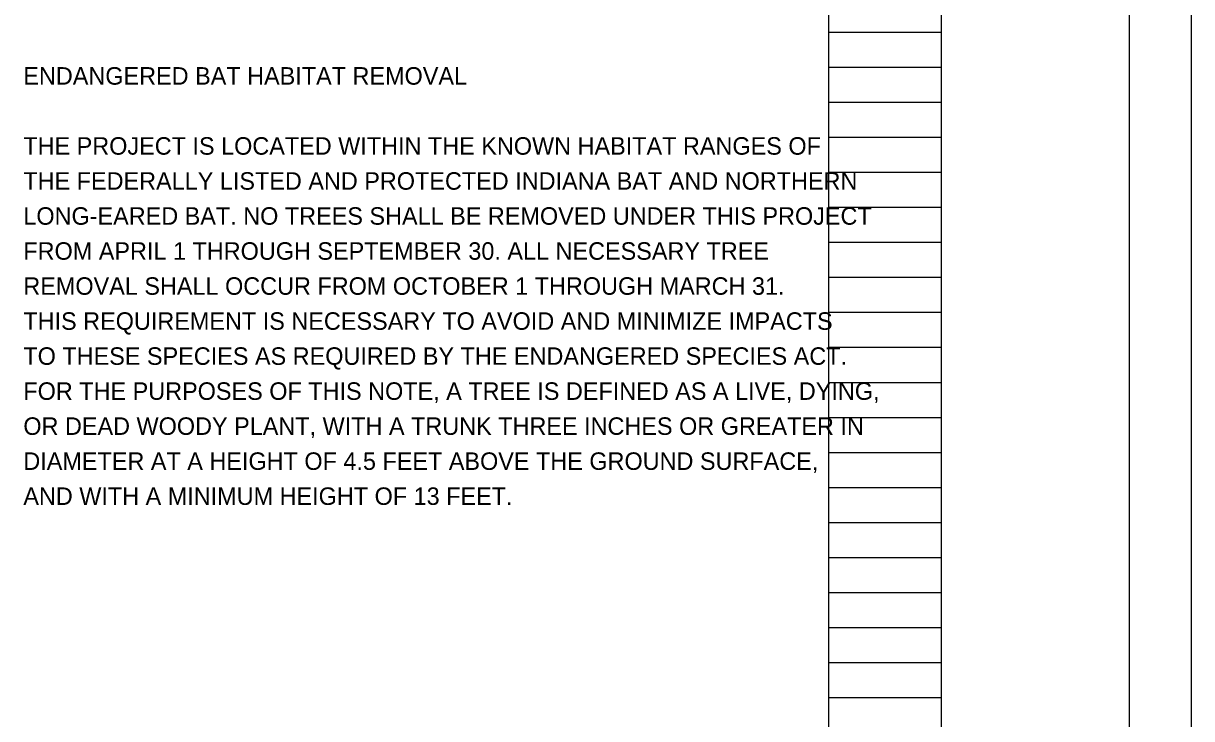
# Model space of a CAD drawing. Extents: x 0 to 84.3, y -13.4 to 22.
# Drawn here: x 24.66 to 34, y 5.57 to 11.13 of the extents above; entities that cross this region are included whole.
import ezdxf

# ---------------------------------------------------------------- set-up
doc = ezdxf.new("R2010")
doc.units = 0
for name, color, linetype in [('SH_Border', 7, 'Continuous'), ('SH_Cut_Line', 7, 'Continuous'), ('SH_Data', 7, 'Continuous'), ('SH_Text', 7, 'Continuous')]:
    doc.layers.add(name, color=color, linetype=linetype)

msp = doc.modelspace()

# ---------------------------------------------------------------- linework, layer by layer
at = {"layer": 'SH_Border'}
msp.add_line((32, 0.5), (32, 21.5), dxfattribs=at)
msp.add_lwpolyline([(1.5, 21.5), (33.5, 21.5), (33.5, 0.5), (1.5, 0.5)], close=True, dxfattribs=at)
at = {"layer": 'SH_Cut_Line'}
msp.add_lwpolyline([(0, 0), (34, 0), (34, 22), (0, 22)], close=True, dxfattribs=at)
at = {"layer": 'SH_Data'}
for p, q in [((31.1, 0.98), (31.1, 21.14)), ((32, 0.98), (32, 21.14)), ((31.1, 11.06), (32, 11.06)), ((31.1, 10.78), (32, 10.78)), ((31.1, 10.5), (32, 10.5)), ((31.1, 10.22), (32, 10.22)), ((31.1, 9.94), (32, 9.94)), ((31.1, 9.66), (32, 9.66)), ((31.1, 9.38), (32, 9.38)), ((31.1, 9.1), (32, 9.1)), ((31.1, 8.82), (32, 8.82)), ((31.1, 8.54), (32, 8.54)), ((31.1, 8.26), (32, 8.26)), ((31.1, 7.98), (32, 7.98)), ((31.1, 7.7), (32, 7.7)), ((31.1, 7.42), (32, 7.42)), ((31.1, 7.14), (32, 7.14)), ((31.1, 6.86), (32, 6.86)), ((31.1, 6.58), (32, 6.58)), ((31.1, 6.3), (32, 6.3)), ((31.1, 6.02), (32, 6.02)), ((31.1, 5.74), (32, 5.74))]:
    msp.add_line(p, q, dxfattribs=at)

# ---------------------------------------------------------------- texts
at = {"layer": 'SH_Text'}
for s, p in [('ENDANGERED BAT HABITAT REMOVAL', (24.66, 10.64)), ('THE PROJECT IS LOCATED WITHIN THE KNOWN HABITAT RANGES OF ', (24.66, 10.08)), ('THE FEDERALLY LISTED AND PROTECTED INDIANA BAT AND NORTHERN', (24.66, 9.8)), ('LONG-EARED BAT. NO TREES SHALL BE REMOVED UNDER THIS PROJECT', (24.66, 9.52)), ('FROM APRIL 1 THROUGH SEPTEMBER 30. ALL NECESSARY TREE ', (24.66, 9.24)), ('REMOVAL SHALL OCCUR FROM OCTOBER 1 THROUGH MARCH 31.', (24.66, 8.96)), ('THIS REQUIREMENT IS NECESSARY TO AVOID AND MINIMIZE IMPACTS', (24.66, 8.68)), ('TO THESE SPECIES AS REQUIRED BY THE ENDANGERED SPECIES ACT.', (24.66, 8.4)), ('FOR THE PURPOSES OF THIS NOTE, A TREE IS DEFINED AS A LIVE, DYING,', (24.66, 8.12)), ('OR DEAD WOODY PLANT, WITH A TRUNK THREE INCHES OR GREATER IN', (24.66, 7.84)), ('DIAMETER AT A HEIGHT OF 4.5 FEET ABOVE THE GROUND SURFACE,', (24.66, 7.56)), ('AND WITH A MINIMUM HEIGHT OF 13 FEET.', (24.66, 7.28))]:
    msp.add_text(s, height=0.14, dxfattribs=at).set_placement(p)

doc.saveas('drawing.dxf')
